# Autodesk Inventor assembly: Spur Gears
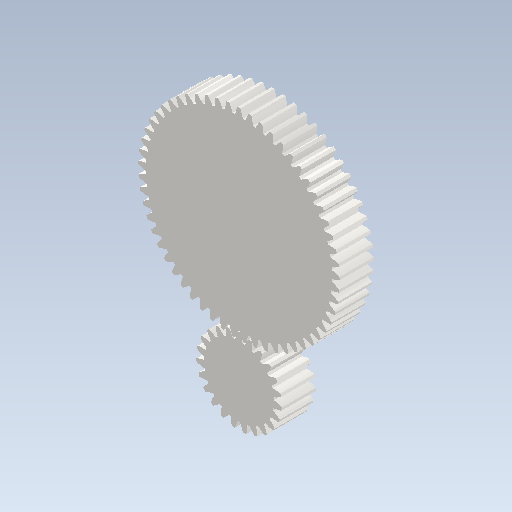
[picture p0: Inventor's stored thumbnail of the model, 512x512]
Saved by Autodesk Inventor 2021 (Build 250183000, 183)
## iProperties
ClientObjectVersion: 1
Created: 2026-10
Part Number: Spur Gears
Document SubType Name: Assembly
Designer: hp
Categories: <?xml version="1.0" encoding="UTF-16"?> <MemberInstance><Categories><FamilyTemplate/><ParamToTemplateMap><ParamToTemplate><ParamToTemplate CategoryParameter="//
Author: hp
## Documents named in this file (3)
- C:\Users\hp\Documents\Inventor\DOM1_CartesianRobot\Probably Base\Design Accelerator\Spur Gears1.iam
- C:\Users\hp\Documents\Inventor\DOM1_CartesianRobot\Probably Base\Design Accelerator\Spur Gear11.ipt
- C:\Users\hp\Documents\Inventor\DOM1_CartesianRobot\Probably Base\Design Accelerator\Spur Gear21.ipt
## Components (2 placed, 2 different names)
1. Spur Gear1:1 — Rotation:1
2. Spur Gear2:1 — Rotation:1
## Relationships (1: RelateRotation 1)
- Rotation:1 [RelateRotation]: Spur Gear1:1 ↔ Spur Gear2:1
